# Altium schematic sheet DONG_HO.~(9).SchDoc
size A
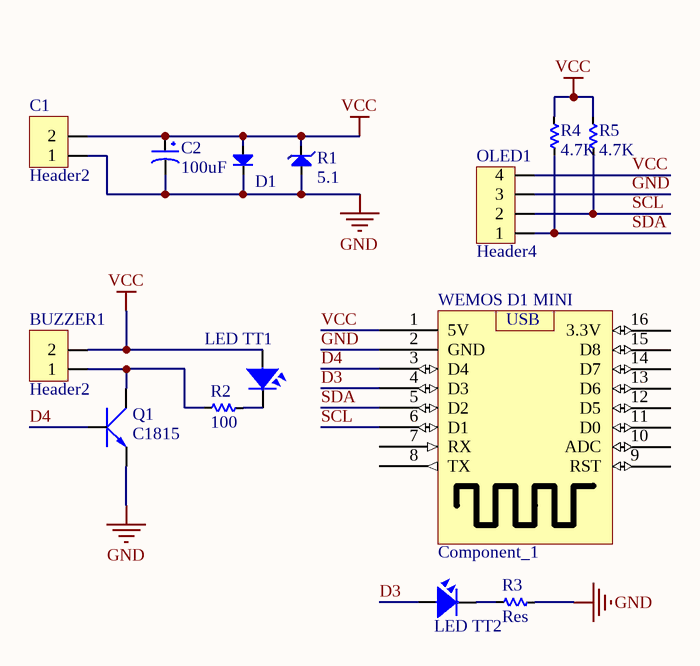
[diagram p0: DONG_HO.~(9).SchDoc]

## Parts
BUZZER1  Header2  [Header2]
C1  Header2  [Header2]
C2  100uF  [CP1/2.5]
D1  Diode  [DIO-1A-SMALL]  (value not drawn)
LED_TT1  LED  [LED-3MM-YELLOW]  (value not drawn)
LED_TT2  LED  [LED-3MM-YELLOW]  (value not drawn)
OLED1  Header4  [Header4]
Q1  C1815  [QTO-92]
R1  5.1  [DIO-1A-ZEN]
R2  100  [RES-1/8W-SMALL]
R3  Res  [RES-1/8W-SMALL]
R4  4.7K  [RES-1/8W-SMALL]
R5  4.7K  [RES-1/8W-SMALL]
WEMOS_D1_MINI  Component_1  [ESP WEMOS MINI]

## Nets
GND: C1.1 C2.2 D1.2(K) OLED1.3 Q1.1(E) R1.1(A) R3.2 WEMOS_D1_MINI.2(GND)
VCC: BUZZER1.2 C1.2 C2.1 D1.1(A) LED_TT1.1 OLED1.4 R1.2(K) R4.2 R5.2 WEMOS_D1_MINI.1(5V)
D3: LED_TT2.1 WEMOS_D1_MINI.4(D3)
D4: Q1.3(B) WEMOS_D1_MINI.3(D4)
SCL: OLED1.2 R5.1 WEMOS_D1_MINI.6(D1)
SDA: OLED1.1 R4.1 WEMOS_D1_MINI.5(D2)
NetBUZZER1_1: BUZZER1.1 Q1.2(C) R2.1
NetLED_TT1_2: LED_TT1.2 R2.2
NetLED_TT2_2: LED_TT2.2 R3.1

Not connected (* = marked no-connect by the designer): WEMOS_D1_MINI 7(RX) 8(TX) 9(RST) 10(ADC) 11(D0) 12(D5) 13(D6) 14(D7) 15(D8) 16(3.3V)

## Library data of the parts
BUZZER1 C1 = Header2: Header IDC, 2 x 1 Pin Vertical 2.54mm Pitch (Non-Boxed, Male); Manufacturer: W¨¹rth Elektronik eiSos GmbH; partNo: 613002143121; ComponentLink1 Description: Manufacturer; ComponentLink2 Description: Datasheet; NoPins: 02
C2 = CP2: C 47uF/50V , 220uF/16V; Value: 47uF/16 - 50V; Description 1: 470uF/6,3V - 330uF/10V - 220uF/16V; Description 2: 100uF/25V - 35V - 47uF/50V - 22uF/100V; Description 3: 33uF => 47uF/63V - 1uF => 4,7uF/160V; Description 4: 1uF => 2,2uF/250V - 1uF/350V
D1 = Diode: Default Diode; Code - JEDEC: DO-214-AB; Value: 1N5007
LED_TT1 LED_TT2 = LED: LED Single colour Green and Red; Value: LED 3 ly Single Colour
OLED1 = Header4: Header IDC, 4 x 1 Pin Vertical 2.54mm Pitch (Non-Boxed, Male); Manufacturer: W¨¹rth Elektronik eiSos GmbH; partNo: 613002143121; ComponentLink1 Description: Manufacturer; ComponentLink2 Description: Datasheet; NoPins: 02
Q1 = C1815: NPN 600mW, ECB
R1 = DIODE Zener: Zenner
R2-R5 = Res: Manufacturer: Generic Components; Class: Passive; SubClass: R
